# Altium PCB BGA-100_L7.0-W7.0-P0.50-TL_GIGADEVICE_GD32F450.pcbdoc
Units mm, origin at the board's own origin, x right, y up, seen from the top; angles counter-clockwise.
Board outline 20.2 x 19.76 mm, 2 copper layers (Top Layer, Bottom Layer), stack 0 mm thick; 1 components, 0 nets, 100 pads, 0 vias.
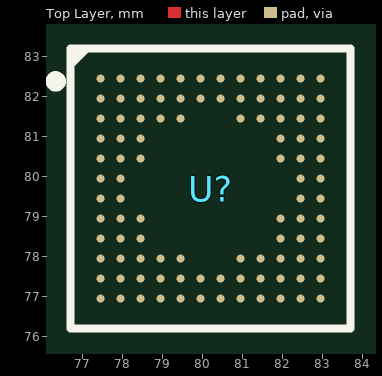
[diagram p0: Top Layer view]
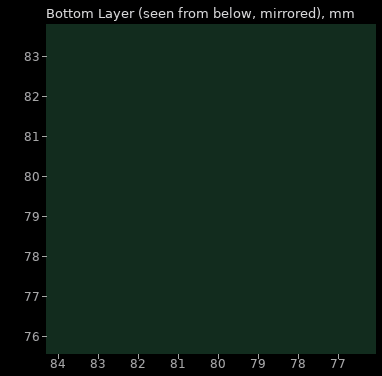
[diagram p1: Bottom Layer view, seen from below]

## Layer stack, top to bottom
Top Layer: signal copper (thickness not stored)
Bottom Layer: signal copper (thickness not stored)

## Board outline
90.047,69.85 69.85,69.85 69.85,89.61 90.047,89.61

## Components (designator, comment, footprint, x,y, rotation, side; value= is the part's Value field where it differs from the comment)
U? "" BGA-100_L7.0-W7.0-P0.50-TL_GIGADEVICE_GD32F450 80.197,79.7 r0 top

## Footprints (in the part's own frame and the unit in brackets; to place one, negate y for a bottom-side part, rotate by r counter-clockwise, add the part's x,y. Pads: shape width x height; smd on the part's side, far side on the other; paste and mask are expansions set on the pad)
BGA-100_L7.0-W7.0-P0.50-TL_GIGADEVICE_GD32F450 [mm]
  round 0.2 smd: A1(-2.75,2.75) A2(-2.25,2.75) A3(-1.75,2.75) A4(-1.25,2.75) A5(-0.75,2.75) A6(-0.25,2.75) A7(0.25,2.75) A8(0.75,2.75) A9(1.25,2.75) A10(1.75,2.75) A11(2.25,2.75) A12(2.75,2.75) B1(-2.75,2.25) B2(-2.25,2.25) B3(-1.75,2.25) B4(-1.25,2.25) B5(-0.75,2.25) B6(-0.25,2.25) B7(0.25,2.25) B8(0.75,2.25) B9(1.25,2.25) B10(1.75,2.25) B11(2.25,2.25) B12(2.75,2.25) C1(-2.75,1.75) C2(-2.25,1.75) C3(-1.75,1.75) C4(-1.25,1.75) C5(-0.75,1.75) C8(0.75,1.75) C9(1.25,1.75) C10(1.75,1.75) C11(2.25,1.75) C12(2.75,1.75) D1(-2.75,1.25) D2(-2.25,1.25) D3(-1.75,1.25) D10(1.75,1.25) D11(2.25,1.25) D12(2.75,1.25) E1(-2.75,0.75) E2(-2.25,0.75) E3(-1.75,0.75) E10(1.75,0.75) E11(2.25,0.75) E12(2.75,0.75) F1(-2.75,0.25) F2(-2.25,0.25) F11(2.25,0.25) F12(2.75,0.25) G1(-2.75,-0.25) G2(-2.25,-0.25) G11(2.25,-0.25) G12(2.75,-0.25) H1(-2.75,-0.75) H2(-2.25,-0.75) H3(-1.75,-0.75) H10(1.75,-0.75) H11(2.25,-0.75) H12(2.75,-0.75) J1(-2.75,-1.25) J2(-2.25,-1.25) J3(-1.75,-1.25) J10(1.75,-1.25) J11(2.25,-1.25) J12(2.75,-1.25) K1(-2.75,-1.75) K2(-2.25,-1.75) K3(-1.75,-1.75) K4(-1.25,-1.75) K5(-0.75,-1.75) K8(0.75,-1.75) K9(1.25,-1.75) K10(1.75,-1.75) K11(2.25,-1.75) K12(2.75,-1.75) L1(-2.75,-2.25) L2(-2.25,-2.25) L3(-1.75,-2.25) L4(-1.25,-2.25) L5(-0.75,-2.25) L6(-0.25,-2.25) L7(0.25,-2.25) L8(0.75,-2.25) L9(1.25,-2.25) L10(1.75,-2.25) L11(2.25,-2.25) L12(2.75,-2.25) M1(-2.75,-2.75) M2(-2.25,-2.75) M3(-1.75,-2.75) M4(-1.25,-2.75) M5(-0.75,-2.75) M6(-0.25,-2.75) M7(0.25,-2.75) M8(0.75,-2.75) M9(1.25,-2.75) M10(1.75,-2.75) M11(2.25,-2.75) M12(2.75,-2.75)
  silkscreen extent -4,-3.5 3.5,3.5

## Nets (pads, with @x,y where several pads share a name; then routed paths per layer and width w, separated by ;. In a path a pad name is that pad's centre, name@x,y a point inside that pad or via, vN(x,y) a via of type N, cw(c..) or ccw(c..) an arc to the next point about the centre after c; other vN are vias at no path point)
pads on no net: U?.A1 U?.A2 U?.A3 U?.A4 U?.A5 U?.A6 U?.A7 U?.A8 U?.A9 U?.A10 U?.A11 U?.A12 U?.B1 U?.B2 U?.B3 U?.B4 U?.B5 U?.B6 U?.B7 U?.B8 U?.B9 U?.B10 U?.B11 U?.B12 U?.C1 U?.C2 U?.C3 U?.C4 U?.C5 U?.C8 U?.C9 U?.C10 U?.C11 U?.C12 U?.D1 U?.D2 U?.D3 U?.D10 U?.D11 U?.D12 U?.E1 U?.E2 U?.E3 U?.E10 U?.E11 U?.E12 U?.F1 U?.F2 U?.F11 U?.F12 U?.G1 U?.G2 U?.G11 U?.G12 U?.H1 U?.H2 U?.H3 U?.H10 U?.H11 U?.H12 U?.J1 U?.J2 U?.J3 U?.J10 U?.J11 U?.J12 U?.K1 U?.K2 U?.K3 U?.K4 U?.K5 U?.K8 U?.K9 U?.K10 U?.K11 U?.K12 U?.L1 U?.L2 U?.L3 U?.L4 U?.L5 U?.L6 U?.L7 U?.L8 U?.L9 U?.L10 U?.L11 U?.L12 U?.M1 U?.M2 U?.M3 U?.M4 U?.M5 U?.M6 U?.M7 U?.M8 U?.M9 U?.M10 U?.M11 U?.M12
